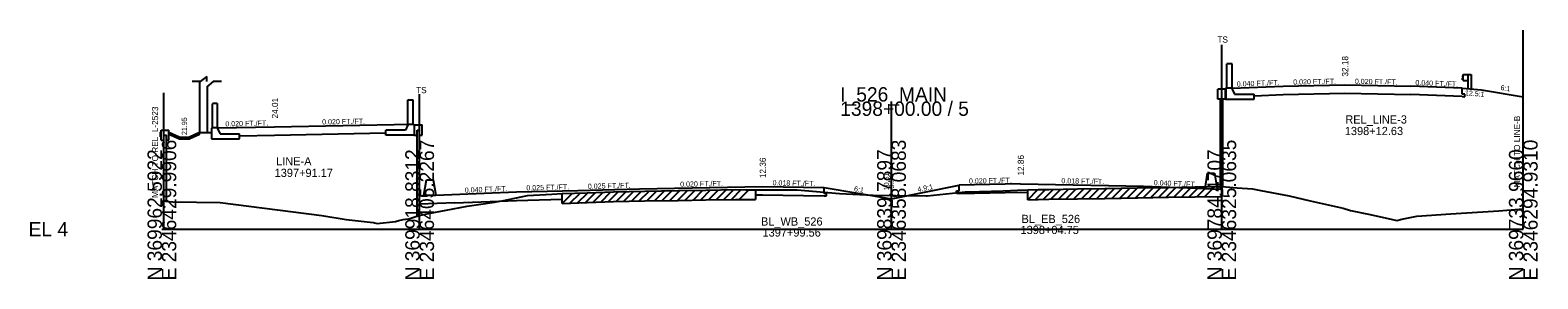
# Model space of a CAD drawing. Extents: x -170 to 2527928, y -10 to 1619750.
# Drawn here: x 1974.3 to 2268.4, y 7990.3 to 8038.9 of the extents above; entities that cross this region are included whole.
import ezdxf

# ---------------------------------------------------------------- set-up
doc = ezdxf.new("R2010")
doc.units = 0
for name, color, linetype in [('Default', 7, 'Continuous'), ('RD_GPK_XS_Cell', 7, 'Continuous'), ('RD_PD_NOISE-WALL-GM', 7, 'Continuous'), ('RD_PD_WallFill', 7, 'Continuous'), ('RD_XS_Base', 7, 'Continuous'), ('RD_XS_EarthShd', 7, 'Continuous'), ('RD_XS_ExGround', 7, 'Continuous'), ('RD_XS_ExPaveRet', 7, 'Continuous'), ('RD_XS_GR', 7, 'Continuous'), ('RD_XS_MatchLine', 7, 'Continuous'), ('RD_XS_Pave', 7, 'Continuous'), ('RD_XS_PaveShd', 7, 'Continuous'), ('RD_XS_TieSlope', 7, 'Continuous'), ('RD_XS_TX_Elev_EX', 7, 'Continuous'), ('RD_XS_TX_Elev_PR', 7, 'Continuous'), ('RD_XS_TX_Slope', 7, 'Continuous'), ('RD_XS_TX_Station', 7, 'Continuous')]:
    doc.layers.add(name, color=color, linetype=linetype)

msp = doc.modelspace()

# ---------------------------------------------------------------- linework, layer by layer
at = {"layer": 'Default'}
for p, q in [((2007.5, 8028.82), (2005.92, 8028.82)), ((2008.75, 8029.84), (2007.5, 8028.82)), ((2008.75, 8028.82), (2008.75, 8029.84)), ((2010, 8028.82), (2008.75, 8027.79)), ((2011.6, 8028.82), (2010, 8028.82))]:
    msp.add_line(p, q, dxfattribs=at)
at = {"layer": 'RD_GPK_XS_Cell'}
for p, q in [((2142.32, 8000), (2142.32, 8024.93)), ((2000, 8000), (2050.28, 8000)), ((2050.28, 8000), (2142.32, 8000)), ((2142.32, 8000), (2206.74, 8000)), ((2206.74, 8000), (2265.55, 8000))]:
    msp.add_line(p, q, dxfattribs=at)
at = {"layer": 'RD_PD_NOISE-WALL-GM'}
for p, q in [((2007.37, 8028.82), (2007.37, 8018.87)), ((2008.87, 8018.87), (2008.87, 8027.89)), ((2203.49, 8007.94), (2203.97, 8010.94)), ((2203.97, 8010.94), (2205.31, 8010.94)), ((2205.31, 8010.94), (2205.81, 8007.85)), ((2051.12, 8006.65), (2051.6, 8009.65)), ((2051.6, 8009.65), (2052.94, 8009.65)), ((2052.94, 8009.65), (2053.42, 8006.65)), ((2051.12, 8006.65), (2053.42, 8006.65))]:
    msp.add_line(p, q, dxfattribs=at)
at = {"layer": 'RD_PD_WallFill'}
for p, q in [((2207.74, 8027.54), (2207.74, 8032.29)), ((2208.74, 8032.29), (2207.74, 8032.29)), ((2208.74, 8027.54), (2208.74, 8032.29)), ((2205.96, 8025.37), (2205.96, 8027.37)), ((2207.46, 8027.37), (2205.96, 8027.37)), ((2207.61, 8027.54), (2207.44, 8027.37)), ((2207.46, 8025.37), (2207.46, 8027.37)), ((2207.53, 8027.37), (2207.46, 8027.37)), ((2207.53, 8027.45), (2207.53, 8025.37)), ((2208.74, 8027.54), (2207.61, 8027.54)), ((2208.74, 8027.54), (2208.74, 8027.37)), ((2208.74, 8027.37), (2209.23, 8026.37)), ((2209.23, 8026.37), (2213.03, 8026.37)), ((2213.03, 8025.37), (2213.03, 8026.37)), ((2009.96, 8024.54), (2009.87, 8024.46)), ((2009.87, 8019.79), (2009.87, 8024.46)), ((2010.79, 8024.54), (2009.96, 8024.54)), ((2010.79, 8024.54), (2010.87, 8024.46)), ((2010.87, 8019.79), (2010.87, 8024.46)), ((2048.08, 8025.28), (2048, 8025.2)), ((2048, 8020.53), (2048, 8025.2)), ((2048.08, 8025.28), (2048.92, 8025.28)), ((2048.92, 8025.28), (2049, 8025.2)), ((2049, 8020.53), (2049, 8025.2)), ((2206.46, 8025.37), (2205.96, 8025.37)), ((2206.46, 8007.83), (2206.46, 8025.37)), ((2206.96, 8008.31), (2206.96, 8025.37)), ((2207.46, 8025.37), (2206.96, 8025.37)), ((2207.46, 8025.37), (2213.03, 8025.37)), ((2207.53, 8025.37), (2207.46, 8025.37)), ((2009.75, 8019.79), (2009.66, 8019.7)), ((2009.66, 8019.7), (2009.66, 8017.62)), ((2010.87, 8019.79), (2009.75, 8019.79)), ((2010.87, 8019.79), (2010.87, 8019.62)), ((2048, 8020.36), (2047.51, 8019.36)), ((2048, 8020.53), (2049.13, 8020.53)), ((2048, 8020.53), (2048, 8020.36)), ((2049.13, 8020.53), (2049.3, 8020.36)), ((2049.21, 8020.45), (2049.21, 8018.36)), ((2049.21, 8020.36), (2049.28, 8020.36)), ((2049.28, 8018.36), (2049.28, 8020.36)), ((2049.28, 8020.36), (2050.78, 8020.36)), ((2050.78, 8018.36), (2050.78, 8020.36)), ((1999.87, 8019.37), (2001.37, 8019.37)), ((1999.87, 8017.37), (1999.87, 8019.37)), ((1999.87, 8017.37), (2000.37, 8017.37)), ((2000.37, 8005.51), (2000.37, 8018.37)), ((2000.37, 8018.37), (2000.87, 8018.37)), ((2000.87, 8005.47), (2000.87, 8018.37)), ((2000.87, 8017.37), (2001.37, 8017.37)), ((2001.37, 8017.37), (2001.37, 8019.37)), ((2003.37, 8017.95), (2001.37, 8018.87)), ((2003.3, 8017.62), (2001.37, 8018.5)), ((2003.3, 8017.62), (2005.45, 8017.62)), ((2003.37, 8017.95), (2005.37, 8017.95)), ((2007.37, 8018.87), (2005.37, 8017.95)), ((2007.37, 8018.5), (2005.45, 8017.62)), ((2007.37, 8018.5), (2007.37, 8018.87)), ((2009.66, 8017.62), (2015.16, 8017.62)), ((2010.87, 8019.62), (2011.37, 8018.62)), ((2011.37, 8018.62), (2015.16, 8018.62)), ((2015.16, 8017.62), (2015.16, 8018.62)), ((2047.51, 8019.36), (2043.71, 8019.36)), ((2043.71, 8018.36), (2043.71, 8019.36)), ((2049.28, 8018.36), (2043.71, 8018.36)), ((2049.21, 8018.36), (2049.28, 8018.36)), ((2049.28, 8018.36), (2049.78, 8018.36)), ((2049.78, 8019.36), (2050.28, 8019.36)), ((2049.78, 8002.57), (2049.78, 8019.36)), ((2050.28, 8002.67), (2050.28, 8019.36)), ((2050.28, 8018.36), (2050.78, 8018.36)), ((2203.49, 8007.94), (2206.46, 8007.83))]:
    msp.add_line(p, q, dxfattribs=at)
at = {"layer": 'RD_XS_Base'}
for p, q in [((2213.03, 8026.07), (2218.74, 8026.3)), ((2218.74, 8026.3), (2230.74, 8026.54)), ((2230.74, 8026.54), (2243.64, 8026.28)), ((2253.64, 8025.88), (2243.64, 8026.28)), ((2253.64, 8026.38), (2253.64, 8027.52)), ((2254.14, 8026.36), (2253.64, 8026.38)), ((2253.64, 8025.88), (2254.14, 8025.86)), ((2254.14, 8025.86), (2254.14, 8026.36)), ((2015.16, 8018.24), (2022, 8018.37)), ((2022, 8018.37), (2043.71, 8018.81)), ((2129.16, 8007), (2129.16, 8008.14)), ((2155.49, 8007.48), (2155.49, 8008.62)), ((2050.28, 8004.88), (2050.28, 8006.52)), ((2057.16, 8005.16), (2050.28, 8004.88)), ((2057.16, 8005.16), (2069.16, 8005.64)), ((2069.16, 8005.64), (2078.1, 8005.86)), ((2115.78, 8006.69), (2117.16, 8006.72)), ((2117.16, 8006.72), (2129.16, 8006.5)), ((2129.66, 8006.99), (2129.16, 8007)), ((2129.16, 8006.5), (2129.66, 8006.49)), ((2129.66, 8006.49), (2129.66, 8006.99)), ((2154.99, 8007.47), (2155.49, 8007.48)), ((2154.99, 8006.97), (2154.99, 8007.47)), ((2155.49, 8006.98), (2154.99, 8006.97)), ((2155.49, 8006.98), (2167.49, 8007.22)), ((2167.49, 8007.22), (2168.88, 8007.2))]:
    msp.add_line(p, q, dxfattribs=at)
at = {"layer": 'RD_XS_EarthShd'}
for p, q in [((2253.64, 8027.52), (2257.39, 8027.22)), ((2007.37, 8018.87), (2009.66, 8018.87))]:
    msp.add_line(p, q, dxfattribs=at)
at = {"layer": 'RD_XS_ExGround'}
msp.add_lwpolyline([(2000, 8005.55), (2002.15, 8005.35), (2011.36, 8005.23), (2031.18, 8002.7), (2035.92, 8001.93), (2041.23, 8001.3), (2042.01, 8001.11), (2045.55, 8001.51), (2046.19, 8001.7), (2047.05, 8001.87), (2047.57, 8001.96), (2048.16, 8002.03), (2049.56, 8002.5), (2050.28, 8002.67), (2051.99, 8003.07), (2055.44, 8003.72), (2059.54, 8004.5), (2064.86, 8005.31), (2065.92, 8005.48), (2066.36, 8005.55), (2068.84, 8006.09), (2071.34, 8006.6), (2076.08, 8006.82), (2078.1, 8006.95), (2082.93, 8007.12), (2088.08, 8007.33), (2094.21, 8007.44), (2100.68, 8007.56), (2106.12, 8007.65), (2111.87, 8007.74), (2113.89, 8007.72), (2115.78, 8007.69), (2118.36, 8007.68), (2123.89, 8007.68), (2132.19, 8006.95), (2138.71, 8006.63), (2142.32, 8006.61), (2143.11, 8006.61), (2149.1, 8006.53), (2149.13, 8006.53), (2149.28, 8006.54), (2156.68, 8007.3), (2159.49, 8007.37), (2164.13, 8007.5), (2166.88, 8007.62), (2168.88, 8007.69), (2170.91, 8007.73), (2173.01, 8007.77), (2178.61, 8007.86), (2183.95, 8007.94), (2190.28, 8008.06), (2196.33, 8008.17), (2201.49, 8008.25), (2206.74, 8008.31), (2209.72, 8008.1), (2212.72, 8007.86), (2214.33, 8007.55), (2219.86, 8006.5), (2223.99, 8005.53), (2230.42, 8004.12), (2231.82, 8003.67), (2235.66, 8002.89), (2240.05, 8001.88), (2240.88, 8001.72), (2241.89, 8001.99), (2244.81, 8002.57), (2251.43, 8003), (2252.47, 8003.07), (2260.81, 8003.58), (2265.55, 8003.95)], dxfattribs=at)
at = {"layer": 'RD_XS_ExPaveRet'}
for p, q in [((2177.88, 8005.93), (2179.83, 8007.88)), ((2179.38, 8005.96), (2181.33, 8007.9)), ((2180.88, 8005.98), (2182.83, 8007.92)), ((2182.38, 8006), (2184.33, 8007.95)), ((2183.88, 8006.02), (2185.83, 8007.97)), ((2185.38, 8006.05), (2187.33, 8008)), ((2186.88, 8006.08), (2188.83, 8008.03)), ((2188.38, 8006.1), (2190.33, 8008.06)), ((2189.88, 8006.13), (2191.83, 8008.09)), ((2191.38, 8006.16), (2193.33, 8008.11)), ((2192.88, 8006.19), (2194.83, 8008.14)), ((2194.38, 8006.22), (2196.33, 8008.17)), ((2195.88, 8006.24), (2197.83, 8008.19)), ((2197.38, 8006.27), (2199.33, 8008.21)), ((2198.88, 8006.29), (2200.83, 8008.24)), ((2200.38, 8006.31), (2202.33, 8008.26)), ((2201.88, 8006.34), (2203.82, 8008.28)), ((2203.38, 8006.35), (2205.32, 8008.29)), ((2206.74, 8008.31), (2206.74, 8006.39)), ((2078.1, 8005.03), (2080.08, 8007.02)), ((2078.1, 8005.03), (2078.1, 8006.95)), ((2078.1, 8005.03), (2082.93, 8005.2)), ((2079.6, 8005.08), (2081.58, 8007.07)), ((2081.1, 8005.14), (2083.09, 8007.13)), ((2082.6, 8005.19), (2084.59, 8007.19)), ((2082.93, 8005.2), (2088.08, 8005.42)), ((2084.1, 8005.25), (2086.1, 8007.25)), ((2085.6, 8005.31), (2087.6, 8007.31)), ((2087.1, 8005.38), (2089.07, 8007.35)), ((2088.08, 8005.42), (2094.21, 8005.52)), ((2088.6, 8005.43), (2090.55, 8007.38)), ((2090.1, 8005.45), (2092.05, 8007.4)), ((2091.6, 8005.48), (2093.55, 8007.43)), ((2093.1, 8005.51), (2095.05, 8007.46)), ((2094.21, 8005.52), (2100.68, 8005.64)), ((2094.6, 8005.53), (2096.55, 8007.49)), ((2096.1, 8005.56), (2098.05, 8007.51)), ((2097.6, 8005.59), (2099.55, 8007.54)), ((2099.1, 8005.62), (2101.05, 8007.57)), ((2100.6, 8005.64), (2102.54, 8007.59)), ((2100.68, 8005.64), (2106.12, 8005.73)), ((2102.1, 8005.67), (2104.04, 8007.62)), ((2103.6, 8005.69), (2105.54, 8007.64)), ((2105.1, 8005.71), (2107.04, 8007.66)), ((2106.12, 8005.73), (2111.87, 8005.82)), ((2106.6, 8005.74), (2108.54, 8007.69)), ((2108.1, 8005.76), (2110.04, 8007.71)), ((2109.6, 8005.78), (2111.54, 8007.73)), ((2111.1, 8005.81), (2113.01, 8007.73)), ((2111.87, 8005.82), (2113.89, 8005.8)), ((2112.6, 8005.81), (2114.49, 8007.71)), ((2113.89, 8005.8), (2115.78, 8005.78)), ((2115.78, 8007.69), (2115.78, 8005.78)), ((2168.88, 8005.77), (2170.84, 8007.73)), ((2168.88, 8005.77), (2168.88, 8007.69)), ((2168.88, 8005.77), (2170.91, 8005.81)), ((2170.38, 8005.8), (2172.34, 8007.76)), ((2170.91, 8005.81), (2173.01, 8005.85)), ((2171.88, 8005.83), (2173.83, 8007.78)), ((2173.01, 8005.85), (2178.61, 8005.95)), ((2173.38, 8005.86), (2175.33, 8007.81)), ((2174.88, 8005.88), (2176.83, 8007.83)), ((2176.38, 8005.91), (2178.33, 8007.86)), ((2178.61, 8005.95), (2183.95, 8006.02)), ((2183.95, 8006.02), (2190.28, 8006.14)), ((2190.28, 8006.14), (2196.33, 8006.25)), ((2196.33, 8006.25), (2201.49, 8006.33)), ((2201.49, 8006.33), (2206.74, 8006.39))]:
    msp.add_line(p, q, dxfattribs=at)
at = {"layer": 'RD_XS_GR'}
for p, q in [((2253.81, 8030.1), (2253.64, 8029.9)), ((2253.64, 8029.9), (2253.64, 8029.85)), ((2253.64, 8029.85), (2253.81, 8029.65)), ((2253.64, 8029.33), (2253.81, 8029.53)), ((2253.64, 8029.28), (2253.64, 8029.33)), ((2253.81, 8029.08), (2253.64, 8029.28)), ((2253.81, 8029.01), (2253.81, 8030.18)), ((2253.81, 8030.18), (2254.73, 8030.18)), ((2253.81, 8029.01), (2254.73, 8029.01)), ((2254.73, 8030.18), (2255.39, 8030.18)), ((2254.73, 8030.18), (2254.73, 8027.43)), ((2255.39, 8030.18), (2255.39, 8027.38))]:
    msp.add_line(p, q, dxfattribs=at)
at = {"layer": 'RD_XS_MatchLine'}
for p, q in [((2265.55, 8000), (2265.55, 8038.87)), ((2206.74, 8000), (2206.74, 8035.97)), ((2000.37, 8000), (2000.37, 8026.65)), ((2050.28, 8000), (2050.28, 8026.39))]:
    msp.add_line(p, q, dxfattribs=at)
at = {"layer": 'RD_XS_Pave'}
for p, q in [((2218.74, 8027.94), (2230.74, 8028.18)), ((2230.74, 8028.18), (2243.64, 8027.92)), ((2022, 8020.01), (2048.65, 8020.54)), ((2081.16, 8007.58), (2093.16, 8007.88)), ((2093.16, 8007.88), (2117.16, 8008.36)), ((2167.49, 8008.86), (2191.49, 8008.42)), ((2069.16, 8007.28), (2081.16, 8007.58))]:
    msp.add_line(p, q, dxfattribs=at)
at = {"layer": 'RD_XS_PaveShd'}
for p, q in [((2208.74, 8027.54), (2218.74, 8027.94)), ((2253.64, 8027.52), (2243.64, 8027.92)), ((2010.87, 8019.79), (2022, 8020.01)), ((2117.16, 8008.36), (2129.16, 8008.14)), ((2167.49, 8008.86), (2155.49, 8008.62)), ((2191.49, 8008.42), (2203.49, 8007.94)), ((2050.28, 8006.52), (2069.16, 8007.28))]:
    msp.add_line(p, q, dxfattribs=at)
at = {"layer": 'RD_XS_TieSlope'}
for p, q in [((2257.39, 8027.22), (2265.55, 8025.86)), ((2129.16, 8008.14), (2142.32, 8005.94)), ((2142.32, 8005.94), (2155.49, 8008.62))]:
    msp.add_line(p, q, dxfattribs=at)

# ---------------------------------------------------------------- texts
at = {"layer": 'RD_GPK_XS_Cell'}
for s, p in [('I_526_MAIN', (2132.32, 8024.93)), ('1398+00.00 / 5', (2132.32, 8022.13)), ('EL 4', (1974, 7998.6))]:
    msp.add_text(s, height=2.8, dxfattribs=at).set_placement(p)
for s, p in [('E 2346429.9906', (2002.8, 7990)), ('E 2346405.2267', (2053.08, 7990)), ('E 2346358.0683', (2145.12, 7990)), ('E 2346325.0635', (2209.54, 7990)), ('E 2346294.9310', (2268.35, 7990)), ('N 369962.5922', (2000, 7990)), ('N 369918.8312', (2050.28, 7990)), ('N 369839.7897', (2142.32, 7990)), ('N 369784.4707', (2206.74, 7990)), ('N 369733.9660', (2265.55, 7990))]:
    msp.add_text(s, height=2.8, rotation=90, dxfattribs=at).set_placement(p)
at = {"layer": 'RD_XS_MatchLine'}
for p in [(2205.89, 8036.43), (2049.59, 8026.56)]:
    msp.add_text('TS', height=1.2, dxfattribs=at).set_placement(p)
for s, p in [('MATCH TO REL_L-2523', (1999.27, 8006.11)), ('MATCH TO LINE-B', (2264.93, 8008.16))]:
    msp.add_text(s, height=1.2, rotation=90, dxfattribs=at).set_placement(p)
at = {"layer": 'RD_XS_TX_Elev_EX'}
msp.add_text('10.61', height=1, rotation=90, dxfattribs=at).set_placement((2141.82, 8007.61))
at = {"layer": 'RD_XS_TX_Elev_PR'}
msp.add_text('9.94', height=1, rotation=90, dxfattribs=at).set_placement((2142.82, 8007.94))
at = {"layer": 'RD_XS_TX_Slope'}
for s, rotation, p in [('0.040 FT./FT.', 2.2906, (2209.68, 8027.83)), ('0.020 FT./FT.', 1.1458, (2220.68, 8028.23)), ('0.020 FT./FT.', 358.8542, (2232.69, 8028.39)), ('0.040 FT./FT.', 357.7094, (2244.48, 8028.14)), ('12.5:1', 355.4261, (2254.14, 8026.14)), ('6:1', 350.5377, (2261.05, 8027.2)), ('21.95', 90, (2004.89, 8018.39)), ('0.020 FT./FT.', 1.1458, (2012.38, 8020.07)), ('0.020 FT./FT.', 1.1458, (2031.27, 8020.44)), ('0.040 FT./FT.', 2.2906, (2059.1, 8007.12)), ('0.025 FT./FT.', 1.4321, (2071.1, 8007.57)), ('0.025 FT./FT.', 1.4321, (2083.1, 8007.87)), ('0.020 FT./FT.', 1.1458, (2101.1, 8008.28)), ('0.018 FT./FT.', 358.9639, (2119.11, 8008.57)), ('6:1', 350.5377, (2134.95, 8007.43)), ('4.9:1', 11.483, (2147.48, 8007.25)), ('0.020 FT./FT.', 1.1458, (2157.43, 8008.91)), ('0.018 FT./FT.', 358.9643, (2175.44, 8008.97)), ('0.040 FT./FT.', 357.7094, (2193.45, 8008.6))]:
    msp.add_text(s, height=1, rotation=rotation, dxfattribs=at).set_placement(p)
at = {"layer": 'RD_XS_TX_Station'}
for s, p in [(' 32.18', (2231.4, 8029.35)), (' 24.01', (2022.66, 8021.18)), (' 12.36', (2117.81, 8009.53)), (' 12.86', (2168.15, 8010.03))]:
    msp.add_text(s, height=1.2, rotation=90, dxfattribs=at).set_placement(p)
for s, p in [('1398+12.63', (2230.74, 8018.38)), ('REL_LINE-3', (2230.84, 8020.63)), ('LINE-A', (2022.29, 8012.46)), ('1397+91.17', (2022, 8010.21)), ('BL_WB_526', (2116.86, 8000.71)), ('BL_EB_526', (2167.68, 8001.21)), ('1397+99.56', (2117.16, 7998.56)), ('1398+04.75', (2167.49, 7999.06))]:
    msp.add_text(s, height=1.6, dxfattribs=at).set_placement(p)

doc.saveas('drawing.dxf')
